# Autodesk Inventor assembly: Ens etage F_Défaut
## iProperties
Shininess: 64.0
Length Units: 11269
Angle Units: 11279
Time Units: 11290
Mass Units: 11283
Length Display Precision: 3
Angle Display Precision: 2
Compacted: True
Created: 2006-01
Part Number: Ens etage F_Défaut
Document SubType Name: Assembly
Designer: Fricot
Density: 0.0
Volumn: 0.0
Area: 0.0
PropertySet Name: Model Information
Control State: 0
Master: False
Checked Out: False
Author: Fricot
